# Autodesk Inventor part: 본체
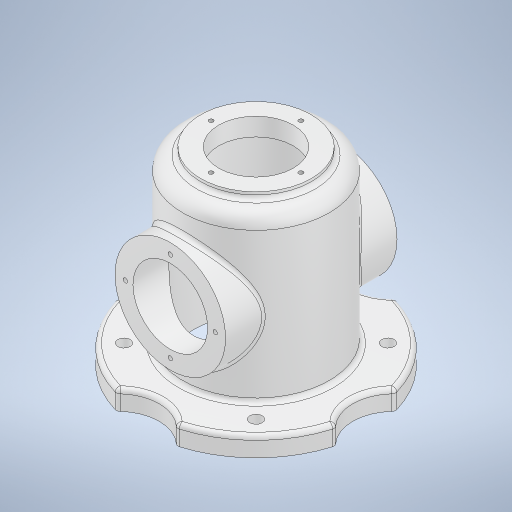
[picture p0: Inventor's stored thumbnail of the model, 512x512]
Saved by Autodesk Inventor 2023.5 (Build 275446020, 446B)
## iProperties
Created: 2026-07
Part Number: 본체
Material: 알루미늄 6061
Document SubType Name: Modeling
Designer: mirae
Mass: 1642.9 g
Surface Area: 1267.78 cm^2
Volume: 608.482 cm^3
Density: 2.7 g/cm^3
Appearance: 알루미늄 - 평지
Author: mirae
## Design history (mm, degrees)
sketch "스케치1"
  geometry: L1 (0, 0)-(0, -55.788); L2 (0, 0)-(37.571, 0); C1 r 30 at (-100, 0); A1 r 30 centre (100, 0) between (79.12, -21.541) and (79.12, 21.541); A2 r 30 centre (0, -100) between (-21.541, -79.12) and (21.541, -79.12); A3 r 82 centre (0, 0) between (21.541, -79.12) and (79.12, -21.541); A4 r 30 centre (0, 100) between (21.541, 79.12) and (-21.541, 79.12); A5 r 82 centre (0, 0) between (79.12, 21.541) and (21.541, 79.12); A6 r 82 centre (0, 0) between (-21.541, 79.12) and (-21.541, -79.12); 3 further points
  constraints: 12 point on circle, 7 centre point, 4 end point, 2 symmetric about line, 1 coincident, 1 horizontal, 1 horizontal alignment, 1 point on line, 1 vertical, 2 other
  dimensions: "d1" = 60 diameter of A1; "d3" = 100 distance of point (0, 0) A1.centre; "d4" = 60 diameter of A2; "d5" = 100 distance of point (0, 0) A2.centre; "d7" = 82 radius of A3; "d8" = 82 radius of A6; "d9" = 82 radius of A5
extrude "돌출1" new body sketch "스케치1" distance "d10" = 14; taper "d11" = 0 deg
sketch "스케치2"
  geometry: C1 r 53 at (0, 0); 1 further point
  constraints: 1 centre point, 1 coincident
  dimensions: "d12" = 106 diameter of C1
extrude "돌출2" join sketch "스케치2" distance "d13" = 132; taper "d14" = 0 deg
sketch "스케치3"
  geometry: C1 r 40 at (0, 0); 1 further point
  constraints: 1 centre point, 1 coincident
  dimensions: "d15" = 80 diameter of C1
extrude "돌출3" join sketch "스케치3" distance "d16" = 5; taper "d17" = 0 deg
node "작업 평면1"
sketch "스케치4"
  geometry: L1 (53, 132)-(-53, 132) reference; L2 (-53, 14)-(53, 14) reference; L3 (53, 14)-(53, 132) reference; L4 (-21.541, 0)-(21.541, 0) reference; C1 r 40 at (0, 68); 2 further points
  constraints: 1 centre point, 1 midpoint, 1 vertical alignment
  dimensions: "d19" = 80 diameter of C1; "d20" = 68 distance from line of L4 C1.centre
extrude "돌출4" join sketch "스케치4" stored distance "d21" = 5; taper "d22" = 0 deg
sketch "스케치5"
  geometry: L1 (0, 0)-(14.926, 0); L2 (0, 0)-(0, 16.586); C1 r 40 at (0, 0) reference; A1 r 32.5 centre (0, 0) between (0, 32.5) and (32.5, 0); 3 further points
  constraints: 4 end point, 4 point on circle, 2 horizontal alignment, 2 vertical alignment, 1 centre point, 1 coincident, 1 horizontal, 1 vertical
  dimensions: "d23" = 65 diameter of A1
hole "구멍1" sketch "스케치5" at (0, 32.5), (32.5, 0), (0, -32.5), (-32.5, 0) diameter "d24" = 3.242; stored, may be unused: countersink angle "d28" = 90 deg, drill point angle "d30" = 118 deg; dims "d25" = 8, "d26" = 4, "d27" = 2, "d29" = 10
sketch "스케치6"
  geometry: C1 r 1.621 at (0, -32.5) reference; C2 r 1.621 at (0, 32.5) reference; C3 r 1.621 at (32.5, 0) reference; C4 r 1.621 at (-32.5, 0) reference; C5 r 40 at (0, 0) reference; C6 r 27 at (0, 0); 1 further point
  constraints: 1 centre point, 1 coincident
  dimensions: "d31" = 54 diameter of C6
extrude "돌출5" cut sketch "스케치6" extent not by distance; stored distance "d32" = 0; taper "d33" = 0 deg
sketch "스케치7"
  geometry: C1 r 27 at (0, 0); 1 further point
  constraints: 1 centre point, 1 coincident
  dimensions: "d34" = 54 diameter of C1
extrude "돌출6" cut sketch "스케치7" extent not by distance; stored distance "d35" = 0; taper "d36" = 0 deg
sketch "스케치8"
  geometry: A1 r 32.5 centre (0, 0) between (-32.5, 0) and (0, 32.5); 3 further points
  constraints: 4 point on circle, 2 horizontal alignment, 2 vertical alignment, 1 centre point, 1 coincident
  dimensions: "d37" = 65 diameter of A1
hole "구멍2" sketch "스케치8" at (-32.5, 0), (0, 32.5), (32.5, 0), (0, -32.5) diameter "d38" = 3.242; stored, may be unused: countersink angle "d42" = 90 deg, drill point angle "d44" = 118 deg; dims "d39" = 8, "d40" = 4, "d41" = 2, "d43" = 10
sketch "스케치9"
  geometry: L1 (0, 0)-(-105.357, 0); L2 (0, 0)-(0, 121.247); L3 (0, 0)-(-39.781, 39.781); L4 (0, 0)-(-35.731, -35.731); L5 (0, 0)-(33.645, -33.645); L6 (0, 0)-(37.744, 37.744); A1 r 67.5 centre (0, 0) between (-47.73, -47.73) and (-47.73, 47.73); 3 further points
  constraints: 12 end point, 4 point on circle, 4 point on line, 1 centre point, 1 coincident, 1 horizontal, 1 perpendicular, 1 vertical
  dimensions: "d45" = 135 diameter of A1; "d46" = 45 deg angle of L3 L2; "d47" = 90 deg angle of L4 L3; "d48" = 90 deg angle of L6 L5
hole "구멍3" sketch "스케치9" at (-47.73, -47.73), (-47.73, 47.73), (47.73, 47.73), (47.73, -47.73) diameter "d49" = 9; stored, may be unused: countersink angle "d53" = 90 deg, drill point angle "d55" = 118 deg; dims "d50" = 6, "d51" = 4, "d52" = 2, "d54" = 8
fillet "모깎기1" dims "d56" = 10
fillet "모깎기2" dims "d57" = 3
fillet "모깎기3" dims "d58" = 3
sketch "스케치10"
  geometry: C1 r 45 at (0, 0); 1 further point
  constraints: 1 centre point, 1 coincident
  dimensions: "d59" = 90 diameter of C1
extrude "돌출7" cut sketch "스케치10" distance "d60" = 124; taper "d61" = 0 deg
fillet "모깎기4" dims "d62" = 3
node "작업 평면2"
sketch "스케치11"
  geometry: L1 (0, -20.357)-(0, 20.357) reference; 4 further points
  constraints: 2 midpoint, 1 horizontal alignment, 1 other
  dimensions: "d63" = 70 distance of point (-70, 0) point (0, 0)
feature "엠보싱1" sketch "스케치11" dims "d64" = 0.5, "d65" = 0
fillet "모깎기5" dims "d66" = 3
node "솔리드1"
mirror "미러1"
node "투영된 루프1"
node "투영된 루프2"
node "투영된 루프3"
feature "A9D066F2-1C7D-4E18-AEED-F7BC21143FA4" dims "d49" = 9, "d50" = 6, "d51" = 4, "d52" = 2, "d53" = 90 deg, "d54" = 8, "d55" = 118 deg
other parameters: "d0" = 164, "d6" = 82, "d18" = 62
